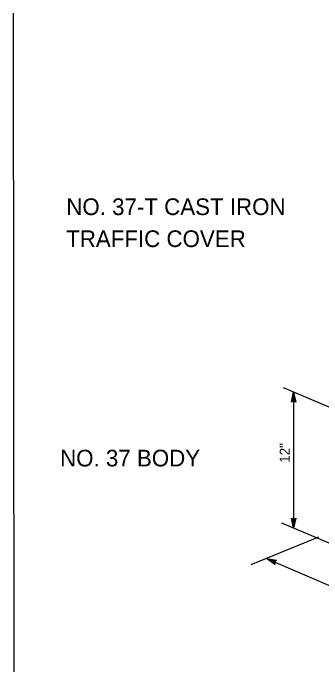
# Model space of a CAD drawing. Extents: x -121875 to -117742, y -103854 to -101122.
# Drawn here: x -121152.3 to -120967, y -101543.8 to -101153.1 of the extents above; entities that cross this region are included whole.
import ezdxf

# ---------------------------------------------------------------- set-up
doc = ezdxf.new("R2010")
doc.units = 0
for name, color, linetype in [('G-MARK', 7, 'Continuous'), ('G-TEXT', 7, 'Continuous'), ('Misc CnstDet(22)', 7, 'Continuous')]:
    doc.layers.add(name, color=color, linetype=linetype)

msp = doc.modelspace()

# ---------------------------------------------------------------- linework, layer by layer
at = {"layer": 'G-MARK'}
for p, q in [((-120957.26, -101391.76), (-120990.02, -101377.76)), ((-120984.03, -101380.32), (-120984.03, -101461.79)), ((-120955.5, -101473.99), (-120991.12, -101458.76)), ((-120969.14, -101467.3), (-121009.66, -101483.86)), ((-121000.34, -101480.05), (-120894.42, -101525.32))]:
    msp.add_line(p, q, dxfattribs=at)
at = {"layer": 'G-TEXT'}
for p, q in [((-120985.37, -101386.32), (-120984.03, -101380.32)), ((-120985.02, -101386.1), (-120984.03, -101381.7)), ((-120984.66, -101385.87), (-120984.03, -101383.08)), ((-120984.03, -101380.32), (-120984.03, -101380.32)), ((-120984.03, -101380.32), (-120982.7, -101386.32)), ((-120984.03, -101381.71), (-120983.06, -101386.08)), ((-120984.03, -101383.08), (-120983.41, -101385.9)), ((-120984.03, -101385.52), (-120985.37, -101386.32)), ((-120985.37, -101386.32), (-120985.37, -101386.32)), ((-120984.31, -101385.69), (-120984.04, -101384.46)), ((-120984.04, -101384.46), (-120983.77, -101385.67)), ((-120982.7, -101386.32), (-120984.03, -101385.52)), ((-120982.7, -101386.32), (-120982.7, -101386.32)), ((-120984.03, -101461.79), (-120985.36, -101455.79)), ((-120985.36, -101455.79), (-120985.36, -101455.79)), ((-120985.36, -101455.79), (-120984.03, -101456.59)), ((-120984.04, -101460.4), (-120985, -101456.03)), ((-120984.03, -101459.03), (-120984.66, -101456.2)), ((-120984.03, -101457.65), (-120984.3, -101456.44)), ((-120984.03, -101456.59), (-120982.69, -101455.79)), ((-120982.69, -101455.79), (-120984.03, -101461.79)), ((-120983.05, -101456.01), (-120984.03, -101460.41)), ((-120983.41, -101456.24), (-120984.03, -101459.03)), ((-120983.75, -101456.42), (-120984.03, -101457.65)), ((-120982.69, -101455.79), (-120982.69, -101455.79)), ((-120984.03, -101461.79), (-120984.03, -101461.79)), ((-120995.3, -101483.57), (-121000.34, -101480.05)), ((-121000.34, -101480.05), (-121000.34, -101480.05)), ((-121000.34, -101480.05), (-120994.28, -101481.1)), ((-120995.36, -101483.16), (-120999.06, -101480.58)), ((-120999.05, -101480.58), (-120994.64, -101481.35)), ((-120995.44, -101482.74), (-120997.78, -101481.1)), ((-120997.78, -101481.1), (-120994.93, -101481.6)), ((-120994.28, -101481.1), (-120995.53, -101482.03)), ((-120994.28, -101481.1), (-120994.28, -101481.1)), ((-120995.47, -101482.35), (-120996.51, -101481.63)), ((-120996.51, -101481.63), (-120995.29, -101481.84)), ((-120995.53, -101482.03), (-120995.3, -101483.57)), ((-120995.3, -101483.57), (-120995.3, -101483.57))]:
    msp.add_line(p, q, dxfattribs=at)
at = {"layer": 'Misc CnstDet(22)'}
msp.add_line((-121152.3, -101153.11), (-121150.94, -102136.14), dxfattribs=at)

# ---------------------------------------------------------------- texts
for s, p in [('NO. 37-T CAST IRON', (-121120.37, -101274.19)), ('TRAFFIC COVER', (-121120.45, -101293.36)), ('NO. 37 BODY', (-121124.07, -101424.84))]:
    msp.add_text(s, height=10, dxfattribs=at).set_placement(p)
msp.add_text('12"', height=6, rotation=90.168, dxfattribs=at).set_placement((-120986.36, -101422.62))

doc.saveas('drawing.dxf')
